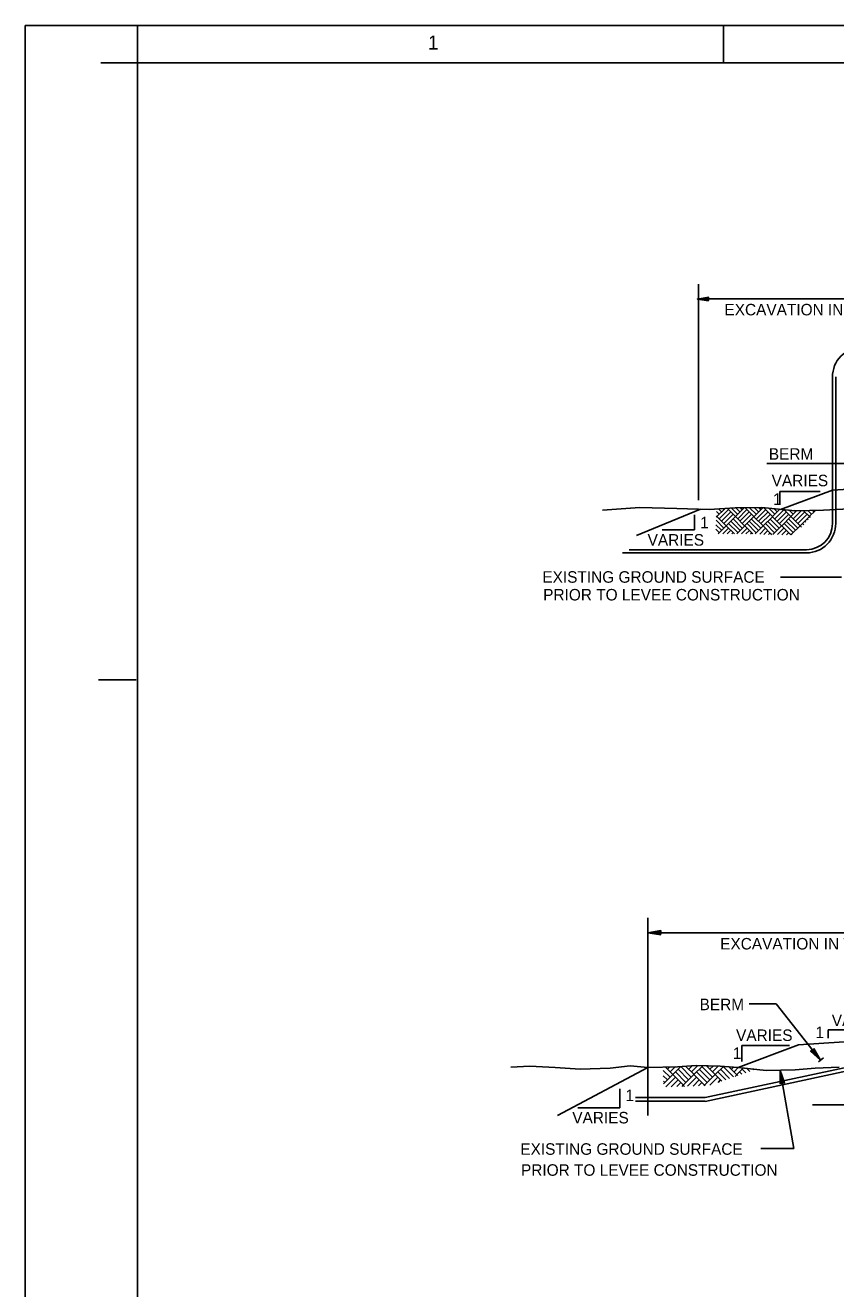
# Model space of a CAD drawing. Extents: x 2127959 to 2137375, y 2146193 to 2153470.
# Drawn here: x 2127959 to 2130277, y 2149857 to 2153470 of the extents above; entities that cross this region are included whole.
import ezdxf

# ---------------------------------------------------------------- set-up
doc = ezdxf.new("R2010")
doc.units = 0
for name, color, linetype in [('Level 1', 7, 'Continuous'), ('Level 3', 7, 'Continuous'), ('Level 5', 7, 'Continuous'), ('Level 50', 7, 'Continuous')]:
    doc.layers.add(name, color=color, linetype=linetype)

msp = doc.modelspace()

# ---------------------------------------------------------------- linework, layer by layer
at = {"layer": 'Level 1'}
for p, q in [((2128280.166, 2153362.032), (2128280.166, 2153469.025)), ((2129956.179, 2153362.032), (2129956.203, 2153469.881)), ((2128175.673, 2153362.032), (2128279.047, 2153362.032)), ((2128280.166, 2146300.478), (2128280.166, 2153362.032)), ((2128280.166, 2153362.032), (2136678.794, 2153362.027)), ((2130080.518, 2152216.542), (2130333.642, 2152216.542)), ((2130861.39, 2152176.343), (2130268.115, 2152140.601)), ((2130861.39, 2152176.343), (2130268.115, 2152140.601)), ((2130861.39, 2152176.343), (2130268.115, 2152140.601)), ((2130268.115, 2152140.601), (2130119.189, 2152085.647)), ((2130268.115, 2152140.601), (2130119.189, 2152085.647)), ((2130268.115, 2152140.601), (2130119.189, 2152085.647)), ((2129890.585, 2152085.946), (2129707.709, 2152010.499)), ((2129890.585, 2152085.946), (2129707.709, 2152010.499)), ((2129890.585, 2152085.946), (2129707.709, 2152010.499)), ((2130294.121, 2151891.491), (2130119.004, 2151891.491)), ((2128168.968, 2151597.921), (2128276.828, 2151597.921)), ((2130106.646, 2150671.698), (2130029.516, 2150671.698)), ((2130233.473, 2150510.795), (2130106.646, 2150671.698)), ((2130715.396, 2150588.701), (2130170.987, 2150554.673)), ((2130170.987, 2150554.673), (2129998.588, 2150490.024)), ((2130228.276, 2150505.902), (2130242.342, 2150517.579)), ((2129739.982, 2150490.024), (2129481.379, 2150352.518)), ((2130118.524, 2150480.816), (2130157.113, 2150257.563)), ((2130157.113, 2150257.563), (2130063.088, 2150257.563))]:
    msp.add_line(p, q, dxfattribs=at)
msp.add_lwpolyline([(2127959.193, 2153469.025), (2137374.681, 2153469.025), (2137374.681, 2146193.484), (2127959.193, 2146193.484)], close=True, dxfattribs=at)
at = {"layer": 'Level 3'}
for p, q in [((2129884.975, 2152111.828), (2129884.975, 2152729.863)), ((2129884.975, 2152687.419), (2130523.327, 2152687.419)), ((2130268.115, 2152464.191), (2130268.115, 2152044.739)), ((2130268.115, 2152464.191), (2130268.115, 2152044.739)), ((2130268.115, 2152464.191), (2130268.115, 2152044.739)), ((2130277.421, 2152464.356), (2130277.421, 2152044.545)), ((2130277.421, 2152464.356), (2130277.421, 2152044.545)), ((2130277.421, 2152464.356), (2130277.421, 2152044.545)), ((2130117.883, 2152136.339), (2130117.883, 2152098.643)), ((2130232.578, 2152136.339), (2130117.883, 2152136.339)), ((2129873.455, 2152026.925), (2129873.455, 2152070.374)), ((2129873.455, 2152026.925), (2129780.567, 2152026.925)), ((2129667.143, 2151961.01), (2130194.088, 2151961.01)), ((2129667.143, 2151961.01), (2130194.088, 2151961.01)), ((2129667.143, 2151961.01), (2130194.088, 2151961.01)), ((2129686.369, 2151970.318), (2130194.136, 2151970.318)), ((2129686.369, 2151970.318), (2130194.136, 2151970.318)), ((2129686.369, 2151970.318), (2130194.136, 2151970.318)), ((2129739.982, 2150490.024), (2129739.982, 2150917.565)), ((2129739.982, 2150875.068), (2130472.692, 2150875.068)), ((2129739.982, 2150875.068), (2130472.692, 2150875.068)), ((2129739.982, 2150875.068), (2130472.692, 2150875.068)), ((2131162.246, 2150673.424), (2129904.058, 2150403.823)), ((2130858.58, 2150597.329), (2129904.058, 2150392.79)), ((2130255.802, 2150597.738), (2130255.802, 2150573.879)), ((2130531.142, 2150597.738), (2130255.802, 2150597.738)), ((2130008.712, 2150552.901), (2130008.712, 2150506.536)), ((2130144.862, 2150552.901), (2130008.712, 2150552.901)), ((2129739.982, 2150490.024), (2129739.982, 2150352.518)), ((2129739.982, 2150490.024), (2129739.982, 2150352.518)), ((2129660.163, 2150374.084), (2129660.163, 2150428.325)), ((2129904.058, 2150403.823), (2129704.345, 2150403.823)), ((2129904.058, 2150393.047), (2129704.345, 2150393.047)), ((2129539.548, 2150374.084), (2129660.163, 2150374.084)), ((2130356.891, 2150382.98), (2130210.728, 2150382.98))]:
    msp.add_line(p, q, dxfattribs=at)
for centre, radius, start, end in [((2130351.887, 2152464.891), 83.772, 90.144292, 180.356647), ((2130351.887, 2152464.891), 83.772, 90.144292, 180.356647), ((2130351.887, 2152464.891), 83.772, 90.144292, 180.356647), ((2130193.651, 2152044.783), 74.464, 270.000508, 359.999483), ((2130193.651, 2152044.783), 74.464, 270.000508, 359.999483), ((2130193.651, 2152044.783), 74.464, 270.000508, 359.999483), ((2130193.654, 2152044.781), 83.577, 270.196219, 0.470075), ((2130193.654, 2152044.781), 83.577, 270.196219, 0.470075), ((2130193.654, 2152044.781), 83.577, 270.196219, 0.470075)]:
    msp.add_arc(centre, radius, start, end, dxfattribs=at)
at = {"layer": 'Level 5'}
for p, q in [((2129610.368, 2152082.952), (2129716.708, 2152091.129)), ((2129610.368, 2152082.952), (2129716.708, 2152091.129)), ((2129610.368, 2152082.952), (2129716.708, 2152091.129)), ((2129716.708, 2152091.129), (2129823.349, 2152088.24)), ((2129716.708, 2152091.129), (2129823.349, 2152088.24)), ((2129716.708, 2152091.129), (2129823.349, 2152088.24)), ((2129914.968, 2152085.126), (2129990.067, 2152089.685)), ((2129914.968, 2152085.126), (2129990.067, 2152089.685)), ((2129914.968, 2152085.126), (2129990.067, 2152089.685)), ((2129990.067, 2152089.685), (2130066.369, 2152091.129)), ((2129990.067, 2152089.685), (2130066.369, 2152091.129)), ((2129990.067, 2152089.685), (2130066.369, 2152091.129)), ((2130015.098, 2152089.921), (2129990.26, 2152065.096)), ((2130005.337, 2152089.489), (2130010, 2152084.827)), ((2130042.959, 2152065.096), (2130017.989, 2152090.057)), ((2130049.523, 2152071.664), (2130031.077, 2152090.102)), ((2130044.755, 2152089.622), (2130056.12, 2152078.263)), ((2130066.369, 2152091.129), (2130161.291, 2152081.27)), ((2130066.369, 2152091.129), (2130161.291, 2152081.27)), ((2130066.369, 2152091.129), (2130161.291, 2152081.27)), ((2129823.349, 2152088.24), (2129914.968, 2152085.126)), ((2129823.349, 2152088.24), (2129914.968, 2152085.126)), ((2129823.349, 2152088.24), (2129914.968, 2152085.126)), ((2129935.408, 2152054.344), (2129957.453, 2152032.285)), ((2129935.778, 2152063.266), (2129937.719, 2152065.216)), ((2129935.933, 2152067.001), (2129937.828, 2152065.096)), ((2129944.305, 2152071.798), (2129936.456, 2152079.645)), ((2129937.717, 2152065.199), (2129959.98, 2152087.479)), ((2129964.041, 2152038.883), (2129937.717, 2152065.199)), ((2129950.88, 2152078.379), (2129942.551, 2152086.707)), ((2129944.278, 2152058.632), (2129970.629, 2152084.993)), ((2129977.203, 2152078.365), (2129950.878, 2152052.036)), ((2129955.187, 2152087.272), (2129957.479, 2152084.977)), ((2129983.801, 2152071.812), (2129957.453, 2152045.464)), ((2129964.041, 2152038.883), (2129990.367, 2152065.199)), ((2129990.367, 2152065.199), (2129967.748, 2152087.822)), ((2129996.828, 2152071.664), (2129980.115, 2152088.371)), ((2129983.801, 2152058.632), (2130010.148, 2152032.285)), ((2129990.367, 2152065.199), (2130016.695, 2152038.883)), ((2129992.744, 2152088.938), (2130003.427, 2152078.263)), ((2129996.96, 2152058.617), (2130023.175, 2152084.827)), ((2130003.535, 2152052.036), (2130029.753, 2152078.263)), ((2130036.35, 2152071.664), (2130010.133, 2152045.436)), ((2130042.914, 2152065.096), (2130016.7, 2152038.87)), ((2130036.877, 2152057.962), (2130063.223, 2152031.616)), ((2130067.746, 2152088.833), (2130043.485, 2152064.575)), ((2130069.81, 2152038.201), (2130043.485, 2152064.53)), ((2130050.047, 2152057.962), (2130076.397, 2152084.308)), ((2130056.648, 2152051.41), (2130082.974, 2152077.739)), ((2130058.376, 2152089.163), (2130062.699, 2152084.827)), ((2130089.571, 2152071.143), (2130063.223, 2152044.797)), ((2130096.138, 2152064.575), (2130069.81, 2152038.242)), ((2130073.125, 2152088.655), (2130096.664, 2152065.111)), ((2130103.275, 2152071.677), (2130086.77, 2152088.18)), ((2130089.571, 2152057.962), (2130115.79, 2152031.75)), ((2130096.138, 2152064.53), (2130122.355, 2152038.316)), ((2130117.789, 2152086.2), (2130096.706, 2152065.111)), ((2130109.825, 2152078.275), (2130100.471, 2152087.628)), ((2130103.275, 2152058.497), (2130129.618, 2152084.843)), ((2130109.87, 2152051.945), (2130136.196, 2152078.275)), ((2130114.86, 2152086.437), (2130116.446, 2152084.843)), ((2130142.79, 2152071.677), (2130116.442, 2152045.334)), ((2130122.918, 2152038.883), (2130149.25, 2152065.216)), ((2130129.22, 2152085.244), (2130149.358, 2152065.111)), ((2130142.637, 2152058.648), (2130168.988, 2152032.303)), ((2130155.838, 2152071.812), (2130143.569, 2152084.069)), ((2130149.245, 2152065.216), (2130166.223, 2152082.192)), ((2130175.571, 2152038.883), (2130149.245, 2152065.216)), ((2130155.813, 2152058.648), (2130178.843, 2152081.686)), ((2130162.412, 2152078.379), (2130157.924, 2152082.878)), ((2130161.291, 2152081.27), (2130242.698, 2152083.189)), ((2130161.291, 2152081.27), (2130242.698, 2152083.189)), ((2130161.291, 2152081.27), (2130242.698, 2152083.189)), ((2130188.735, 2152078.379), (2130162.409, 2152052.05)), ((2130195.333, 2152071.826), (2130168.988, 2152045.464)), ((2130175.571, 2152038.883), (2130201.898, 2152065.216)), ((2130201.898, 2152065.216), (2130185.284, 2152081.836)), ((2130195.333, 2152058.648), (2130198.465, 2152055.505)), ((2130208.358, 2152071.664), (2130197.877, 2152082.133)), ((2130219.339, 2152082.639), (2130201.793, 2152065.096)), ((2130201.898, 2152065.216), (2130204.65, 2152062.476)), ((2130210.78, 2152082.446), (2130214.956, 2152078.263)), ((2130242.698, 2152083.189), (2130333.717, 2152088.477)), ((2130242.698, 2152083.189), (2130333.717, 2152088.477)), ((2130242.698, 2152083.189), (2130333.717, 2152088.477)), ((2129944.281, 2152019.122), (2129934.363, 2152029.041)), ((2129934.887, 2152041.712), (2129950.878, 2152025.72)), ((2129941.04, 2152015.828), (2129964.041, 2152038.841)), ((2129954.093, 2152015.755), (2129970.629, 2152032.285)), ((2129964.041, 2152038.883), (2129987.384, 2152015.547)), ((2129977.203, 2152025.673), (2129967.201, 2152015.668)), ((2129996.975, 2152019.122), (2129970.629, 2152045.464)), ((2130003.531, 2152025.72), (2129977.203, 2152052.036)), ((2129983.801, 2152019.122), (2129980.267, 2152015.592)), ((2129994.437, 2152015.501), (2130017.265, 2152038.316)), ((2130007.495, 2152015.413), (2130023.85, 2152031.779)), ((2130040.382, 2152015.205), (2130017.265, 2152038.316)), ((2130017.265, 2152038.316), (2130040.383, 2152015.205)), ((2130030.426, 2152025.155), (2130020.601, 2152015.323)), ((2130050.05, 2152018.435), (2130023.704, 2152044.797)), ((2130030.32, 2152051.364), (2130056.648, 2152025.035)), ((2130037.024, 2152018.601), (2130033.672, 2152015.251)), ((2130069.81, 2152038.201), (2130046.767, 2152015.159)), ((2130059.869, 2152015.085), (2130076.397, 2152031.616)), ((2130069.81, 2152038.201), (2130093.142, 2152014.877)), ((2130072.933, 2152014.997), (2130082.974, 2152025.035)), ((2130102.615, 2152018.571), (2130076.397, 2152044.797)), ((2130109.189, 2152025.155), (2130082.974, 2152051.364)), ((2130089.571, 2152018.435), (2130086.048, 2152014.923)), ((2130098.877, 2152014.831), (2130122.351, 2152038.305)), ((2130111.93, 2152014.757), (2130128.937, 2152031.768)), ((2130147.276, 2152014.532), (2130122.918, 2152038.883)), ((2130135.516, 2152025.155), (2130125.037, 2152014.671)), ((2130155.813, 2152019.122), (2130129.464, 2152045.464)), ((2130136.082, 2152052.05), (2130162.409, 2152025.72)), ((2130142.111, 2152018.585), (2130138.101, 2152014.58)), ((2130151.229, 2152014.504), (2130175.571, 2152038.841)), ((2130175.571, 2152038.883), (2130179.875, 2152034.582)), ((2130186.071, 2152041.563), (2130182.159, 2152045.464)), ((2130192.262, 2152048.533), (2130188.735, 2152052.05)), ((2130071.808, 2152013.879), (2130072.933, 2152014.997)), ((2130086.048, 2152014.923), (2130084.818, 2152013.686)), ((2130093.142, 2152014.877), (2130094.466, 2152013.552)), ((2130097.542, 2152013.508), (2130098.877, 2152014.831)), ((2130110.49, 2152013.314), (2130111.93, 2152014.757)), ((2130125.037, 2152014.671), (2130123.492, 2152013.12)), ((2130138.101, 2152014.58), (2130136.454, 2152012.94)), ((2130149.051, 2152012.749), (2130147.276, 2152014.532)), ((2130149.476, 2152012.749), (2130151.229, 2152014.504)), ((2129348.258, 2150490.644), (2129402.661, 2150493.66)), ((2129348.258, 2150490.644), (2129402.661, 2150493.66)), ((2129348.258, 2150490.644), (2129402.661, 2150493.66)), ((2129402.661, 2150493.66), (2129475.161, 2150489.283)), ((2129475.161, 2150489.283), (2129546.189, 2150484.49)), ((2129546.189, 2150484.49), (2129632.266, 2150487.439)), ((2129632.266, 2150487.439), (2129689.823, 2150494.177)), ((2129689.823, 2150494.177), (2129739.982, 2150490.024)), ((2129825.145, 2150491.988), (2129739.982, 2150490.024)), ((2129783.713, 2150481.367), (2129803.48, 2150461.612)), ((2129795.818, 2150453.994), (2129784.104, 2150465.714)), ((2129811.106, 2150469.231), (2129784.677, 2150442.802)), ((2129789.074, 2150491.211), (2129811.059, 2150469.231)), ((2129803.109, 2150491.712), (2129795.867, 2150484.473)), ((2129818.896, 2150492.269), (2129803.48, 2150476.851)), ((2129811.106, 2150469.231), (2129834.692, 2150492.819)), ((2129811.106, 2150469.231), (2129841.582, 2150438.751)), ((2129849.078, 2150446.511), (2129818.729, 2150476.851)), ((2129825.145, 2150491.988), (2129877.755, 2150494.853)), ((2129856.695, 2150454.114), (2129826.344, 2150484.473)), ((2129833.983, 2150492.11), (2129864.332, 2150461.767)), ((2129841.45, 2150438.871), (2129871.924, 2150469.353)), ((2129848.001, 2150493.299), (2129872.061, 2150469.231)), ((2129849.212, 2150492.077), (2129850.521, 2150493.387)), ((2129856.828, 2150484.473), (2129865.838, 2150493.475)), ((2129881.153, 2150493.522), (2129864.461, 2150476.837)), ((2129871.924, 2150469.353), (2129896.151, 2150493.575)), ((2129902.404, 2150438.871), (2129871.924, 2150469.353)), ((2129877.755, 2150494.853), (2129947.312, 2150493.249)), ((2129909.882, 2150446.354), (2129879.38, 2150476.851)), ((2129887.043, 2150484.454), (2129917.516, 2150453.994)), ((2129894.631, 2150492.092), (2129925.13, 2150461.595)), ((2129932.754, 2150469.216), (2129902.279, 2150438.751)), ((2129932.754, 2150469.216), (2129908.373, 2150493.609)), ((2129909.882, 2150492.092), (2129911.402, 2150493.63)), ((2129926.73, 2150493.68), (2129917.516, 2150484.454)), ((2129941.352, 2150493.076), (2129925.13, 2150476.851)), ((2129932.754, 2150469.216), (2129955.933, 2150492.385)), ((2129951.382, 2150450.65), (2129932.805, 2150469.216)), ((2129962.642, 2150454.58), (2129940.38, 2150476.851)), ((2129947.312, 2150493.249), (2129998.588, 2150490.024)), ((2129948.044, 2150484.454), (2129973.963, 2150458.545)), ((2129955.632, 2150492.092), (2129985.241, 2150462.475)), ((2129993.76, 2150469.216), (2129971.307, 2150491.677)), ((2129984.643, 2150490.592), (2129979.129, 2150485.074)), ((2129998.566, 2150489.283), (2129986.743, 2150477.474)), ((2129994.368, 2150468.63), (2129989.838, 2150464.096)), ((2129994.368, 2150469.837), (2130012.486, 2150487.972)), ((2129994.976, 2150469.251), (2129997.458, 2150466.751)), ((2129998.588, 2150490.024), (2130078.423, 2150481.3)), ((2130008.758, 2150470.717), (2130002.6, 2150476.87)), ((2130020.043, 2150474.663), (2130010.216, 2150484.473)), ((2130022.993, 2150486.972), (2130031.355, 2150478.609)), ((2130039.787, 2150485.384), (2130042.621, 2150482.56)), ((2130078.423, 2150481.3), (2130161.761, 2150483.146)), ((2130161.761, 2150483.146), (2130218.267, 2150487.938)), ((2130218.267, 2150487.938), (2130286.98, 2150490.803)), ((2129788.23, 2150446.354), (2129784.495, 2150450.095)), ((2129791.127, 2150433.993), (2129818.729, 2150461.612)), ((2129806.815, 2150434.461), (2129826.344, 2150453.994)), ((2129833.983, 2150446.354), (2129822.555, 2150434.924)), ((2129837.95, 2150435.372), (2129841.454, 2150438.89)), ((2129844.754, 2150435.579), (2129841.45, 2150438.871)), ((2129853.607, 2150435.838), (2129879.548, 2150461.787)), ((2129887.164, 2150454.114), (2129869.349, 2150436.306)), ((2129894.804, 2150446.526), (2129885.033, 2150436.769)), ((2129900.754, 2150437.218), (2129902.404, 2150438.871)), ((2129902.404, 2150438.871), (2129903.969, 2150437.32)), ((2129917.608, 2150438.82), (2129940.38, 2150461.595)), ((2129941.028, 2150447.012), (2129947.995, 2150453.994))]:
    msp.add_line(p, q, dxfattribs=at)
at = {"layer": 'Level 50'}
for p, q in [((2129881.932, 2152687.13), (2129881.932, 2152687.13)), ((2129890.816, 2152687.063), (2129890.816, 2152687.063)), ((2129739.742, 2150875.099), (2129739.742, 2150875.099)), ((2129750.021, 2150875.021), (2129750.021, 2150875.021)), ((2130227.035, 2150518.834), (2130227.035, 2150518.834)), ((2130233.473, 2150510.795), (2130233.473, 2150510.795)), ((2130118.524, 2150480.816), (2130118.524, 2150480.816)), ((2130120.231, 2150470.667), (2130120.231, 2150470.667))]:
    msp.add_line(p, q, dxfattribs=at)
for points in [[(2129913.84, 2152681.605), (2129881.932, 2152687.13), (2129913.903, 2152692.202), (2129913.841, 2152683.15), (2129890.816, 2152687.063), (2129912.521, 2152690.501), (2129912.489, 2152684.69), (2129899.351, 2152686.999), (2129911.145, 2152688.802), (2129911.132, 2152686.413), (2129908.238, 2152686.943)], [(2129776.677, 2150868.704), (2129739.742, 2150875.099), (2129776.751, 2150880.969), (2129776.678, 2150870.493), (2129750.021, 2150875.021), (2129775.148, 2150879), (2129775.113, 2150872.272), (2129759.901, 2150874.946), (2129773.555, 2150877.033), (2129773.54, 2150874.27), (2129770.192, 2150874.878)], [(2130215.176, 2150543.526), (2130233.473, 2150510.795), (2130205.614, 2150535.864), (2130213.787, 2150542.387), (2130227.035, 2150518.834), (2130208.15, 2150535.842), (2130213.4, 2150540.064), (2130220.879, 2150526.574), (2130210.682, 2150535.864), (2130212.837, 2150537.58), (2130214.471, 2150534.61)], [(2130118.642, 2150443.33), (2130118.524, 2150480.816), (2130130.73, 2150445.371), (2130120.403, 2150443.628), (2130120.231, 2150470.667), (2130128.514, 2150446.609), (2130121.886, 2150445.482), (2130121.868, 2150460.921), (2130126.308, 2150447.844), (2130123.58, 2150447.369), (2130123.595, 2150450.784)]]:
    msp.add_lwpolyline(points, dxfattribs=at)

# ---------------------------------------------------------------- texts
at = {"layer": 'Level 1'}
for s, height, p in [('1', 40.073, (2129111.355, 2153400.552)), ('EXCAVATION IN THIS AREA TO BE BACKFILLED', 32.931, (2129959.133, 2152640.298)), ('BERM', 32.931, (2130086.093, 2152227.528)), ('VARIES', 32.931, (2130094.134, 2152151.63)), ('1', 32.931, (2130098.003, 2152098.442)), ('1', 32.931, (2129889.538, 2152031.381)), ('VARIES', 32.931, (2129739.311, 2151981.837)), ('EXISTING GROUND SURFACE', 32.931, (2129438.279, 2151875.79)), ('PRIOR TO LEVEE CONSTRUCTION', 32.931, (2129440.646, 2151825.079)), ('EXCAVATION IN THIS AREA TO BE BACKFILLED ', 32.931, (2129946.893, 2150827.068)), ('BERM', 32.931, (2129888.044, 2150653.521)), ('VARIES', 32.931, (2130266.104, 2150607.868)), ('VARIES', 32.931, (2129992.34, 2150565.413)), ('1', 32.931, (2130219.137, 2150573.485)), ('1', 32.931, (2129982.772, 2150514.007)), ('1', 32.931, (2129675.945, 2150393.517)), ('VARIES', 32.931, (2129523.866, 2150329.712)), ('EXISTING GROUND SURFACE', 32.931, (2129375.203, 2150239.997)), ('PRIOR TO LEVEE CONSTRUCTION', 32.931, (2129377.128, 2150179.974))]:
    msp.add_text(s, height=height, dxfattribs=at).set_placement(p)

doc.saveas('drawing.dxf')
